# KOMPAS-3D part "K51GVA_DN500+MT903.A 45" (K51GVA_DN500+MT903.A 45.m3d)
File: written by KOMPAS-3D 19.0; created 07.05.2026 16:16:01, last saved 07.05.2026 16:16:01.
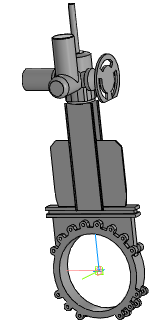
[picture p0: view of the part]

Document properties: Автор: Энергия; Полное имя файла: ..\K51GVA_DN50-DN1000+MT903.A\K51GVA_DN500+MT903.A 45.a3d

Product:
- Part/product: K51GVA_DN500+MT903.A 45
    Масса: 308.61

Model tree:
1. Операция без истории:1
